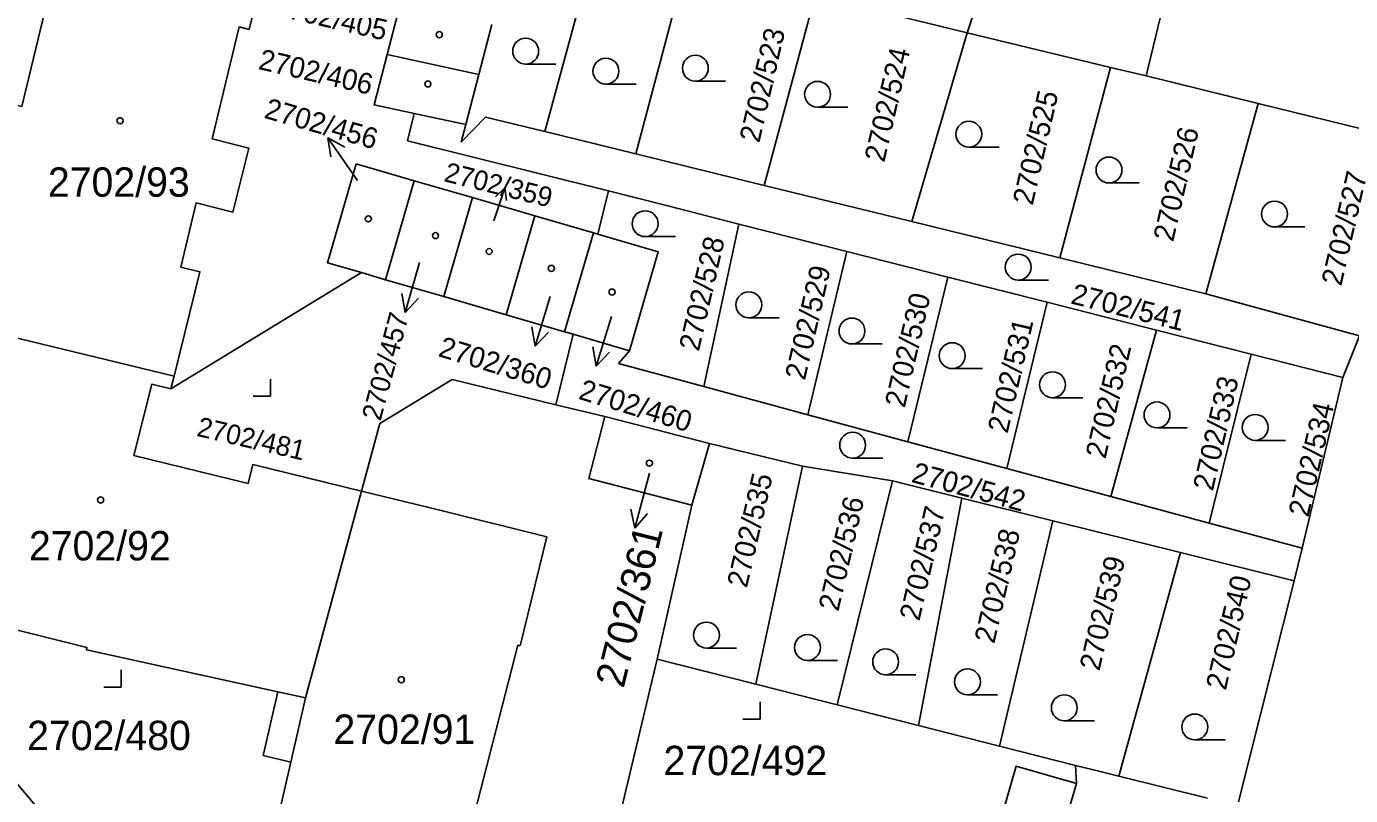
# Model space of a CAD drawing. Extents: x -496682 to -495907, y -1088575 to -1088018.
# Drawn here: x -496634.1 to -496557.4, y -1088524.5 to -1088480 of the extents above; entities that cross this region are included whole.
import ezdxf

# ---------------------------------------------------------------- set-up
doc = ezdxf.new("R2010")
doc.units = 0
for name, color, linetype in [('Hranice parcel', 7, 'Continuous'), ('Parcelní čísla', 7, 'Continuous'), ('Pop  PČ popisy', 7, 'Continuous'), ('Vnitřní kresba', 7, 'Continuous'), ('Značky budov', 7, 'Continuous'), ('Značky kultur', 7, 'Continuous')]:
    doc.layers.add(name, color=color, linetype=linetype)

msp = doc.modelspace()

# ---------------------------------------------------------------- linework, layer by layer
at = {"layer": 'Hranice parcel'}
for p, q in [((-496579.62, -1088480.33), (-496575.06, -1088466.51)), ((-496565.84, -1088468.56), (-496569.26, -1088482.83)), ((-496598.81, -1088487.34), (-496595.91, -1088476.39)), ((-496612.47, -1088478.69), (-496613.22, -1088481.59)), ((-496591.38, -1088489.16), (-496588.43, -1088478.2)), ((-496579.62, -1088480.33), (-496585.4, -1088478.93)), ((-496607.91, -1088482.74), (-496607.16, -1088479.85)), ((-496582.83, -1088491.26), (-496579.62, -1088480.33)), ((-496571.31, -1088482.33), (-496579.62, -1088480.33)), ((-496613.22, -1088481.59), (-496607.91, -1088482.74)), ((-496574.26, -1088493.36), (-496571.31, -1088482.33)), ((-496569.26, -1088482.83), (-496571.31, -1088482.33)), ((-496608.66, -1088485.64), (-496607.91, -1088482.74)), ((-496569.26, -1088482.83), (-496562.76, -1088484.43)), ((-496565.8, -1088495.44), (-496562.76, -1088484.43)), ((-496562.76, -1088484.43), (-496553.34, -1088486.74)), ((-496611.65, -1088485), (-496608.66, -1088485.64)), ((-496608.66, -1088485.64), (-496608.93, -1088486.67)), ((-496604.09, -1088486.04), (-496598.81, -1088487.34)), ((-496611.65, -1088488.89), (-496615.02, -1088487.91)), ((-496598.81, -1088487.34), (-496591.38, -1088489.16)), ((-496613.31, -1088494.62), (-496611.65, -1088488.89)), ((-496608.28, -1088489.87), (-496611.65, -1088488.89)), ((-496600.4, -1088489.48), (-496601.01, -1088491.98)), ((-496591.38, -1088489.16), (-496582.83, -1088491.26)), ((-496608.28, -1088489.87), (-496609.94, -1088495.6)), ((-496604.66, -1088490.92), (-496608.28, -1088489.87)), ((-496606.33, -1088496.65), (-496604.66, -1088490.92)), ((-496601.27, -1088491.9), (-496604.66, -1088490.92)), ((-496594.87, -1088500.81), (-496592.84, -1088491.4)), ((-496586.59, -1088492.99), (-496592.84, -1088491.4)), ((-496582.83, -1088491.26), (-496574.26, -1088493.36)), ((-496602.94, -1088497.63), (-496601.27, -1088491.9)), ((-496601.01, -1088491.98), (-496601.27, -1088491.9)), ((-496588.84, -1088502.44), (-496586.59, -1088492.99)), ((-496580.73, -1088494.47), (-496586.59, -1088492.99)), ((-496574.26, -1088493.36), (-496565.8, -1088495.44)), ((-496614.7, -1088494.21), (-496625.74, -1088500.93)), ((-496614.7, -1088494.21), (-496613.31, -1088494.62)), ((-496613.31, -1088494.62), (-496609.94, -1088495.6)), ((-496583.05, -1088504), (-496580.73, -1088494.47)), ((-496574.99, -1088495.93), (-496580.73, -1088494.47)), ((-496609.94, -1088495.6), (-496606.33, -1088496.65)), ((-496565.8, -1088495.44), (-496556.89, -1088497.88)), ((-496577.33, -1088505.54), (-496574.99, -1088495.93)), ((-496568.66, -1088497.54), (-496574.99, -1088495.93)), ((-496606.33, -1088496.65), (-496602.94, -1088497.63)), ((-496625.56, -1088500.2), (-496637.35, -1088497.34)), ((-496603.45, -1088501.86), (-496602.44, -1088497.78)), ((-496602.94, -1088497.63), (-496602.44, -1088497.78)), ((-496602.44, -1088497.78), (-496599.17, -1088498.73)), ((-496571.29, -1088507.17), (-496568.66, -1088497.54)), ((-496563.16, -1088498.94), (-496568.66, -1088497.54)), ((-496556.89, -1088497.88), (-496557.86, -1088500.28)), ((-496599.17, -1088498.73), (-496599.81, -1088499.48)), ((-496599.81, -1088499.48), (-496594.87, -1088500.81)), ((-496565.6, -1088508.71), (-496563.16, -1088498.94)), ((-496557.86, -1088500.28), (-496563.16, -1088498.94)), ((-496625.74, -1088500.93), (-496625.56, -1088500.2)), ((-496594.87, -1088500.81), (-496588.84, -1088502.44)), ((-496557.86, -1088500.28), (-496560.22, -1088510.16)), ((-496600.61, -1088502.54), (-496603.45, -1088501.86)), ((-496594.55, -1088504.11), (-496600.61, -1088502.54)), ((-496588.84, -1088502.44), (-496583.05, -1088504)), ((-496583.05, -1088504), (-496577.33, -1088505.54)), ((-496595.56, -1088507.68), (-496594.55, -1088504.11)), ((-496589.15, -1088505.41), (-496594.55, -1088504.11)), ((-496591.86, -1088518.03), (-496589.15, -1088505.41)), ((-496583.95, -1088506.27), (-496589.15, -1088505.41)), ((-496577.33, -1088505.54), (-496571.29, -1088507.17)), ((-496587.14, -1088519.23), (-496583.95, -1088506.27)), ((-496579.92, -1088507.27), (-496583.95, -1088506.27)), ((-496597.58, -1088516.58), (-496595.56, -1088507.68)), ((-496582.44, -1088520.43), (-496579.92, -1088507.27)), ((-496574.65, -1088508.58), (-496579.92, -1088507.27)), ((-496571.29, -1088507.17), (-496565.6, -1088508.71)), ((-496577.74, -1088521.62), (-496574.65, -1088508.58)), ((-496567.27, -1088510.42), (-496574.65, -1088508.58)), ((-496565.6, -1088508.71), (-496560.22, -1088510.16)), ((-496560.22, -1088510.16), (-496560.68, -1088512.06)), ((-496570.83, -1088523.36), (-496567.27, -1088510.42)), ((-496560.68, -1088512.06), (-496567.27, -1088510.42)), ((-496560.68, -1088512.06), (-496563.91, -1088524.85)), ((-496601.3, -1088532.22), (-496597.58, -1088516.58)), ((-496591.86, -1088518.03), (-496597.58, -1088516.58)), ((-496587.14, -1088519.23), (-496591.86, -1088518.03)), ((-496582.44, -1088520.43), (-496587.14, -1088519.23)), ((-496577.74, -1088521.62), (-496582.44, -1088520.43)), ((-496573.34, -1088522.74), (-496577.74, -1088521.62)), ((-496573.29, -1088523.79), (-496573.34, -1088522.74)), ((-496575.1, -1088529.97), (-496573.29, -1088523.79)), ((-496570.83, -1088523.36), (-496565.69, -1088524.64))]:
    msp.add_line(p, q, dxfattribs=at)
for points in [[(-496599.74, -1088470.06), (-496599.96, -1088470.85), (-496604.09, -1088486.04)], [(-496637.35, -1088497.34), (-496634.78, -1088486.77), (-496635.48, -1088486.6), (-496634.95, -1088484.46), (-496634.38, -1088484.6), (-496631.65, -1088473.31)], [(-496625.56, -1088500.2), (-496624.06, -1088494.16), (-496625.17, -1088493.89), (-496624.28, -1088490.18), (-496622.15, -1088490.71), (-496621.22, -1088487), (-496623.35, -1088486.47), (-496621.79, -1088479.99), (-496621.21, -1088480.13), (-496619.86, -1088474.64), (-496625.54, -1088473.24), (-496626, -1088474.67), (-496631.65, -1088473.31)], [(-496613.22, -1088481.59), (-496613.97, -1088484.5), (-496611.65, -1088485)], [(-496600.4, -1088489.48), (-496612.03, -1088486.58), (-496611.65, -1088485)], [(-496608.93, -1088486.67), (-496607.51, -1088485.21), (-496604.09, -1088486.04)], [(-496615.02, -1088487.91), (-496616.68, -1088493.64), (-496614.7, -1088494.21)], [(-496592.84, -1088491.4), (-496597.04, -1088490.33), (-496600.4, -1088489.48)], [(-496599.17, -1088498.73), (-496597.51, -1088493), (-496601.01, -1088491.98)], [(-496625.74, -1088500.93), (-496626.84, -1088500.66), (-496627.88, -1088504.8), (-496621.27, -1088506.42), (-496621, -1088505.32), (-496614.7, -1088506.86)], [(-496603.45, -1088501.86), (-496609.45, -1088500.4), (-496613.64, -1088502.94), (-496614.7, -1088506.86)], [(-496595.56, -1088507.68), (-496601.53, -1088506.12), (-496600.61, -1088502.54)], [(-496614.7, -1088506.86), (-496617.94, -1088518.83), (-496619.55, -1088518.48)], [(-496621.83, -1088538.93), (-496627.8, -1088531.94), (-496637.3, -1088520.68), (-496644.5, -1088512.3)], [(-496619.55, -1088518.48), (-496630.64, -1088516.04), (-496630.61, -1088515.92), (-496641.69, -1088513.15), (-496641.66, -1088513.05)], [(-496619.55, -1088518.48), (-496620.39, -1088522.17), (-496618.8, -1088522.54), (-496620.02, -1088527.84), (-496620.32, -1088527.76), (-496621.75, -1088533.36)], [(-496573.29, -1088523.79), (-496576.78, -1088522.78), (-496578.57, -1088528.99), (-496575.1, -1088529.97)], [(-496573.34, -1088522.74), (-496572.3, -1088523), (-496570.83, -1088523.36)]]:
    msp.add_lwpolyline(points, dxfattribs=at)
at = {"layer": 'Pop  PČ popisy'}
for p, q in [((-496614.93, -1088488.87), (-496616.651, -1088486.412)), ((-496616.651, -1088486.412), (-496615.667, -1088486.945)), ((-496616.651, -1088486.412), (-496616.487, -1088487.519)), ((-496607.03, -1088491.21), (-496606.409, -1088489.298)), ((-496606.409, -1088489.298), (-496606.935, -1088489.832)), ((-496606.409, -1088489.298), (-496606.297, -1088490.04)), ((-496611.34, -1088493.63), (-496612.167, -1088496.515)), ((-496612.167, -1088496.515), (-496612.372, -1088495.414)), ((-496603.77, -1088495.59), (-496604.647, -1088498.46)), ((-496612.167, -1088496.515), (-496611.41, -1088495.69)), ((-496600.23, -1088496.75), (-496601.107, -1088499.62)), ((-496604.647, -1088498.46), (-496604.833, -1088497.356)), ((-496604.647, -1088498.46), (-496603.876, -1088497.649)), ((-496601.107, -1088499.62), (-496601.293, -1088498.516)), ((-496601.107, -1088499.62), (-496600.336, -1088498.809)), ((-496598.1, -1088506.1), (-496598.877, -1088508.999)), ((-496598.02, -1088505.81), (-496598.1, -1088506.1)), ((-496598.877, -1088508.999), (-496599.101, -1088507.902)), ((-496598.877, -1088508.999), (-496598.134, -1088508.161))]:
    msp.add_line(p, q, dxfattribs=at)
at = {"layer": 'Vnitřní kresba'}
for p, q in [((-496614.7, -1088506.86), (-496610.25, -1088507.95)), ((-496610.25, -1088507.95), (-496603.96, -1088509.5)), ((-496603.96, -1088509.5), (-496605.52, -1088515.81)), ((-496605.65, -1088515.77), (-496609.45, -1088530.51)), ((-496605.52, -1088515.81), (-496605.65, -1088515.77)), ((-496617.94, -1088518.83), (-496618.8, -1088522.54))]:
    msp.add_line(p, q, dxfattribs=at)
at = {"layer": 'Značky budov'}
for centre in [(-496610.197, -1088480.439), (-496610.857, -1088483.289), (-496628.687, -1088485.419), (-496614.307, -1088491.099), (-496610.417, -1088492.069), (-496607.307, -1088492.989), (-496603.707, -1088493.969), (-496600.187, -1088495.339), (-496598.027, -1088505.239), (-496629.817, -1088507.369), (-496612.397, -1088517.779)]:
    msp.add_circle(centre, 0.175, dxfattribs=at)
at = {"layer": 'Značky kultur'}
for p, q in [((-496605.193, -1088482.14), (-496603.443, -1088482.14)), ((-496600.543, -1088483.3), (-496598.793, -1088483.3)), ((-496595.363, -1088483.13), (-496593.613, -1088483.13)), ((-496588.283, -1088484.64), (-496586.533, -1088484.64)), ((-496579.523, -1088486.95), (-496577.773, -1088486.95)), ((-496571.403, -1088489.02), (-496569.653, -1088489.02)), ((-496561.813, -1088491.57), (-496560.063, -1088491.57)), ((-496598.273, -1088492.13), (-496596.523, -1088492.13)), ((-496576.663, -1088494.64), (-496574.913, -1088494.64)), ((-496592.263, -1088496.83), (-496590.513, -1088496.83)), ((-496586.293, -1088498.34), (-496584.543, -1088498.34)), ((-496580.483, -1088499.77), (-496578.733, -1088499.77)), ((-496619.98, -1088501.37), (-496619.98, -1088500.37)), ((-496620.981, -1088501.37), (-496619.98, -1088501.37)), ((-496574.673, -1088501.45), (-496572.923, -1088501.45)), ((-496568.623, -1088503.2), (-496566.873, -1088503.2)), ((-496562.933, -1088503.92), (-496561.183, -1088503.92)), ((-496586.253, -1088504.95), (-496584.503, -1088504.95)), ((-496594.723, -1088515.94), (-496592.973, -1088515.94)), ((-496588.873, -1088516.66), (-496587.123, -1088516.66)), ((-496628.63, -1088518.21), (-496628.63, -1088517.21)), ((-496584.343, -1088517.49), (-496582.593, -1088517.49)), ((-496629.631, -1088518.21), (-496628.63, -1088518.21)), ((-496579.603, -1088518.65), (-496577.853, -1088518.65)), ((-496591.61, -1088520.06), (-496591.61, -1088519.06)), ((-496592.611, -1088520.06), (-496591.61, -1088520.06)), ((-496573.993, -1088520.15), (-496572.243, -1088520.15)), ((-496566.433, -1088521.26), (-496564.683, -1088521.26))]:
    msp.add_line(p, q, dxfattribs=at)
for centre in [(-496605.193, -1088481.39), (-496600.543, -1088482.55), (-496595.363, -1088482.38), (-496588.283, -1088483.89), (-496579.523, -1088486.2), (-496571.403, -1088488.27), (-496561.813, -1088490.82), (-496598.273, -1088491.38), (-496576.663, -1088493.89), (-496592.263, -1088496.08), (-496586.293, -1088497.59), (-496580.483, -1088499.02), (-496574.673, -1088500.7), (-496568.623, -1088502.45), (-496562.933, -1088503.17), (-496586.253, -1088504.2), (-496594.723, -1088515.19), (-496588.873, -1088515.91), (-496584.343, -1088516.74), (-496579.603, -1088517.9), (-496573.993, -1088519.4), (-496566.433, -1088520.51)]:
    msp.add_circle(centre, 0.75, dxfattribs=at)

# ---------------------------------------------------------------- texts
at = {"layer": 'Parcelní čísla'}
for s, height, rotation, p in [('2702/405', 1.2, 347, (-496619.89, -1088479.28)), ('2702/523', 1.2, 77, (-496591.659, -1088486.74)), ('2702/406', 1.2, 347, (-496620.73, -1088482.42)), ('2702/524', 1.2, 77, (-496584.419, -1088487.87)), ('2702/456', 1.2, 344, (-496620.401, -1088485.24)), ('2702/525', 1.2, 77, (-496575.829, -1088490.36)), ('2702/526', 1.2, 77, (-496567.689, -1088492.47)), ('2702/359', 1.139, 346, (-496609.98, -1088488.912)), ('2702/527', 1.2, 77, (-496557.949, -1088495.03)), ('2702/528', 1.2, 77, (-496595.159, -1088498.81)), ('2702/529', 1.2, 77, (-496589.019, -1088500.49)), ('2702/541', 1.2, 346, (-496573.678, -1088495.985)), ('2702/530', 1.2, 77, (-496583.239, -1088502.08)), ('2702/457', 1.139, 75, (-496613.601, -1088502.844)), ('2702/531', 1.2, 77, (-496577.279, -1088503.56)), ('2702/360', 1.2, 343, (-496610.312, -1088499.034)), ('2702/532', 1.2, 77, (-496571.609, -1088505.03)), ('2702/533', 1.2, 77, (-496565.389, -1088506.9)), ('2702/460', 1.2, 343, (-496602.192, -1088501.504)), ('2702/534', 1.2, 77, (-496559.859, -1088508.41)), ('2702/481', 1.139, 347, (-496624.301, -1088503.656)), ('2702/542', 1.2, 345, (-496582.905, -1088506.321)), ('2702/535', 1.2, 77, (-496592.379, -1088512.51)), ('2702/536', 1.2, 77, (-496587.079, -1088513.86)), ('2702/537', 1.2, 77, (-496582.389, -1088514.42)), ('2702/361', 1.7, 76, (-496599.522, -1088518.316)), ('2702/538', 1.2, 77, (-496578.049, -1088515.73)), ('2702/539', 1.2, 77, (-496571.959, -1088517.31)), ('2702/540', 1.2, 77, (-496564.639, -1088518.43))]:
    msp.add_text(s, height=height, rotation=rotation, dxfattribs=at).set_placement(p)
for s, p in [('2702/93', (-496632.868, -1088489.82)), ('2702/92', (-496633.968, -1088510.87)), ('2702/480', (-496634.07, -1088521.85)), ('2702/91', (-496616.328, -1088521.49)), ('2702/492', (-496597.21, -1088523.3))]:
    msp.add_text(s, height=1.7, dxfattribs=at).set_placement(p)

doc.saveas('drawing.dxf')
